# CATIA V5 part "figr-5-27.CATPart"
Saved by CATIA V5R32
Part number: Part1
Bounding box of the stored display mesh (mm): x -34.542 to 34.542, y -63.781 to 63.781, z 0 to 53
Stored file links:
  D:\PROJECTS\Project 2022\CATIA V5 6R 2022\Resources\Part Files\c05_catia_v5_6r2022_prt\figr-5-27.CATPart
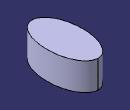
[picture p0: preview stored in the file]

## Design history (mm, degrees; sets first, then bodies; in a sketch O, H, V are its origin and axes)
Body1 (main body)
  Sketch1 on xy-plane, origin (0, 0, 0), H (1, 0, 0), V (0, 1, 0)
    line L1 (-75, 100) -> (75, 100)
    line L2 (75, 100) -> (75, -100)
    line L3 (75, -100) -> (-75, -100)
    line L4 (-75, -100) -> (-75, 100)
    axis line L5 (75, -100) -> (-75, 100)
    length L3 = 150
    length L2 = 200
    horizontal: L1 H, L3 H
    vertical: L2 V, L4 V
    midpoint: L5 O
  Pad1: profile Sketch1, direction (0, 0, 1), length 53
  Sketch2 on face of Pad1, origin (0, 0, 53), H (1, 0, 0), V (0, 1, 0)
    ellipse A1 centre (0, 0) semi-axes 63.781, 34.5424 rotation 270
    point P1 (0, -63.781)
    point P2 (34.5424, 0)
    coincidence: P1 V, P2 H, A1 P1, A1 P2
  Pocket1: profile Sketch2, direction (0, 0, -1), through (limit type 3), outer side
